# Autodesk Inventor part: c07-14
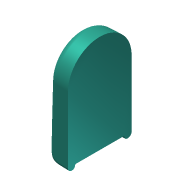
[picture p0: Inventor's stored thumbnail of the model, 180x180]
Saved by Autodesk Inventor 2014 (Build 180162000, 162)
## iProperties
Created: 2010-12
Part Number: c07-14
Material: Generic
Document SubType Name: Modeling
Designer: Thom Tremblay
Density: 1 g/cm^3
Appearance: Smooth - Aqua
Author: Thom Tremblay
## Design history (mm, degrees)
sketch "Sketch1"
  geometry: L1 (-25, 0)-(25, 0); L2 (25, 0)-(25, 80); L3 (25, 80)-(-25, 80); L4 (-25, 80)-(-25, 0); 2 further points
  constraints: 8 end point, 2 parallel, 1 coincident, 1 horizontal, 1 midpoint, 1 perpendicular
  dimensions: "d0" = 50 distance of L3.end L2.end; "d1" = 80 distance of L2.end L1.end
extrude "Extrusion1" new body sketch "Sketch1" distance "d2" = 15; taper "d3" = 0 deg
feature "FaceDraft1" dims angle "d4" = -2 deg
fillet "Fillet1"
fillet "Fillet2" dims "d5" = 8, "d6" = 8, "d7" = 8, "d8" = 8, "d9" = 8, "d10" = 8, "d11" = 3, "d12" = 3, "d13" = 3, "d14" = 6, "d15" = 5
sketch "Sketch2"
  geometry: L1 (5.522, 12)-(38.474, 12) reference; L2 (0, 0)-(43.996, 0) reference; L3 (41.757, 6.83)-(41.995, 0); L4 (41.925, 2)-(2.071, 2); L5 (2.001, 0)-(2.24, 6.83); L6 (5.522, 10)-(38.474, 10); A1 r 5.284 centre (38.474, 6.716) between (43.755, 6.9) and (38.474, 12) reference; A2 r 5.284 centre (5.522, 6.716) between (5.522, 12) and (0.241, 6.9) reference; A3 r 3.284 centre (38.474, 6.716) between (41.757, 6.83) and (38.474, 10); A4 r 3.284 centre (5.522, 6.716) between (5.522, 10) and (2.24, 6.83); 1 further point
  constraints: 8 end point, 4 point on circle, 4 point on line, 2 centre point, 1 other
  dimensions: "d16" = 2 radial gap between concentric circles of A2 A4
extrude "Extrusion2" cut sketch "Sketch2" distance "d17" = 3; taper "d18" = 0 deg
feature "FaceDraft2" dims angle "d19" = 15 deg
sketch "Sketch3" dims "d2" = 15, "d20" = 2.5
  geometry: L1 (16.476, 3)-(-16.476, 3) reference; L2 (16.476, 5.5)-(-16.476, 5.5); 9 further points
  constraints: 2 end point, 2 parallel, 1 horizontal alignment, 19 other
extrude "Extrusion3" cut sketch "Sketch3" distance "d21" = 3; taper "d22" = 0 deg
feature "FaceDraft3" dims angle "d23" = 10 deg
workplane "Work Plane1"
sketch "Sketch4" dims "d1" = 80
  geometry: L1 (41.1, -1.222)-(41.476, -12) reference; L2 (41.476, -12)-(-8.524, -12) reference; L3 (-8.524, -12)-(-8.147, -1.222) reference; L4 (-3.776, 3)-(-1.272, 3) reference; L5 (-0.743, 0)-(33.695, 0) reference; L6 (34.225, 3)-(36.728, 3) reference; L7 (-11.024, -1.804)-(43.976, -1.804); A1 r 90 centre (16.476, -87.5) between (43.976, -1.804) and (-11.024, -1.804); 2 further points
  constraints: 2 end point, 2 point on circle, 1 centre point, 1 midpoint, 1 parallel, 1 vertical alignment, 4 other
  dimensions: "d25" = 90 radius of A1; "d26" = 14.5 distance edge to line of A1 L2; "d27" = 55 distance of L7.start L7.end
extrude_surface "ExtrusionSrf1" sketch "Sketch4" dims "d28" = 86, "d29" = 0
feature "Replace Face1"
fillet "Fillet3" dims "d30" = 1, "d31" = 3
fillet "Fillet4" dims "d32" = 2
body "Solid1"
body "Srf1"
node "Project Cut Edges1" dims "d1" = 80
